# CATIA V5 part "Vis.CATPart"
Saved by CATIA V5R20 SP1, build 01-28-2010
Part number: Vis
Bounding box of the stored display mesh (mm): x -4 to 4, y -4 to 4, z 0 to 32
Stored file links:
  F:\Pro\Emplois\1_Chercheur\ThinkMOTION\MMS\MMS_GR1\abruchon\Catia\Vis.CATPart
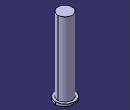
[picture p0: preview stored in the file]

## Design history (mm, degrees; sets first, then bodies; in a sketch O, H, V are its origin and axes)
Body1 (main body)
  Sketch1 on xy-plane, origin (0, 0, 0), H (1, 0, 0), V (0, 1, 0)
    circle A1 centre (0, 0) radius 4
    radius A1 = 4
  Pad1: profile Sketch1, direction (0, 0, 1), length 32
  Sketch2 on end face of Pad1, origin (0, 0, 32), H (1, 0, 0), V (0, 1, 0)
    circle A1 centre (0, 0) radius 3
    point P1 (0, 3)
    radius A1 = 3
    coincidence: A1 P1, P1 V
  Pocket1: profile Sketch2, direction (0, 0, -1), length 31, outer side
  Sketch3 on start face of Pad1, origin (0, 0, 0), H (1, 0, 0), V (0, -1, 0)
    line L1 (-1, 4) -> (-1, -4)
    line L2 (1, -4) -> (1, 4)
    line L3 (1, 4) -> (-1, 4)
    line L4 (1, -4) -> (-1, -4)
    vertical: L1 V, L2 V
    horizontal: L3 H, L4 H
  Pocket2: profile Sketch3, direction (0, 0, 1), length 0.5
